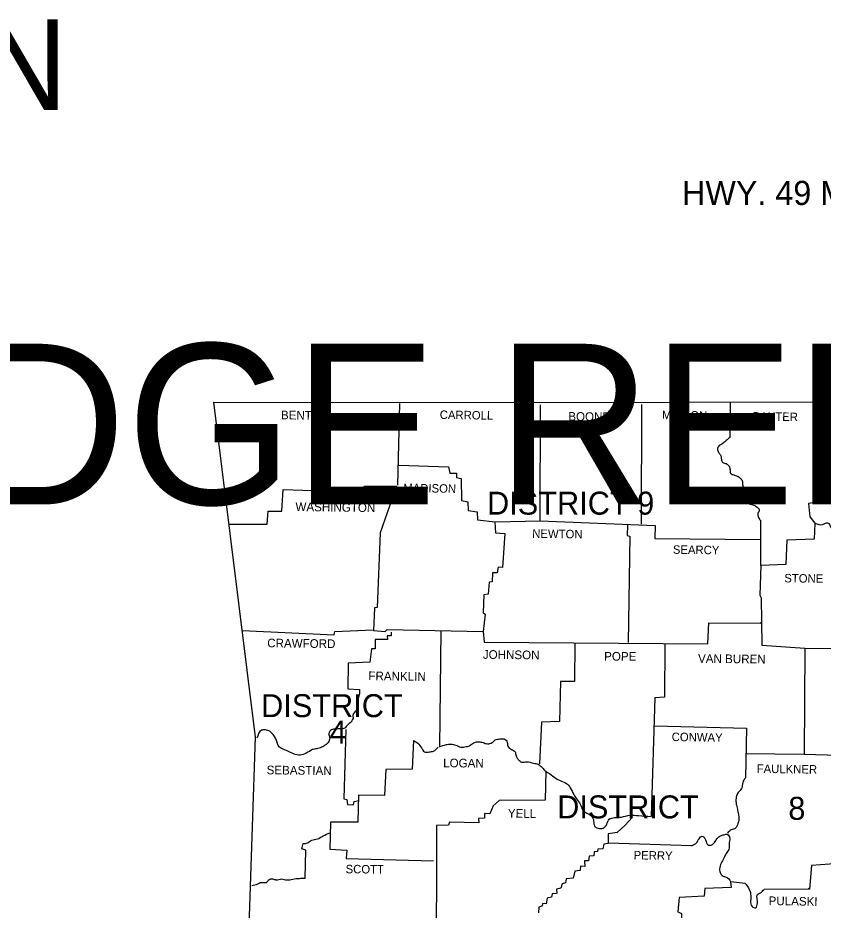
# Model space of a CAD drawing. Extents: x -712 to 3943, y 73 to 2823.
# Drawn here: x 2608.7 to 2999.8, y 1709.8 to 2143 of the extents above; entities that cross this region are included whole.
import ezdxf

# ---------------------------------------------------------------- set-up
doc = ezdxf.new("R2010")
doc.units = 0
for name, color, linetype in [('1', 7, 'Continuous'), ('2', 7, 'Continuous'), ('3', 7, 'Continuous'), ('R_Border', 7, 'Continuous')]:
    doc.layers.add(name, color=color, linetype=linetype)

msp = doc.modelspace()

# ---------------------------------------------------------------- linework, layer by layer
at = {"layer": '1'}
for points in [[(2703.71, 1956.42), (2861.92, 1956.32), (3000.75, 1956.61), (3164.54, 1959.16), (3240.46, 1960.92)], [(2703.71, 1956.42), (2723.96, 1793.81), (2715.15, 1528.37)], [(2794.01, 1955.83), (2793.13, 1916.21)], [(2793.82, 1925.89), (2817.89, 1925.11), (2818.47, 1921.98), (2821.8, 1921.88), (2821.7, 1919.92), (2824.05, 1919.34), (2824.25, 1908.67), (2827.28, 1907.99), (2827.48, 1903.78), (2831.78, 1903.19), (2831.98, 1899.28), (2840.49, 1898.4), (2862.4, 1898.89), (2862.6, 1955.15)], [(2911.62, 1955.34), (2911.33, 1897.22)], [(2954.67, 1956.03), (2954.47, 1939.3)], [(3000.75, 1956.03), (3000.95, 1932.74), (2999.28, 1932.64), (2999.58, 1908.28), (2992.73, 1907.3), (2993.32, 1900.75), (2995.66, 1897.71), (2995.47, 1889.98), (2982.16, 1889.5), (2981.67, 1877.56), (2969.54, 1877.17), (2968.95, 1862.69), (2969.64, 1861.51), (2969.93, 1838.42), (2990.87, 1837.05), (2990.58, 1785.49), (3007.21, 1785), (3007.21, 1732.56), (2994.1, 1731.58), (2993.12, 1720.04), (2971.11, 1719.94)], [(2711.44, 1897.22), (2729.73, 1897.13), (2730.22, 1903.58), (2736.97, 1903.58), (2737.56, 1914.05), (2775.72, 1912.68), (2776.89, 1915.62), (2792.64, 1915.72), (2784.72, 1893.02), (2783.15, 1856.72), (2781.98, 1856.62), (2781.39, 1845.66), (2787.17, 1845.17), (2788.05, 1846.05), (2834.72, 1845.17), (2835.21, 1839.99)], [(2840.29, 1898.2), (2840.68, 1892.92), (2845.18, 1892.63), (2844.01, 1876.19), (2841.96, 1876.29), (2841.56, 1873.65), (2839.22, 1873.65), (2839.12, 1869.14), (2837.65, 1869.05), (2837.16, 1863.27), (2835.01, 1862.98), (2834.72, 1854.17), (2835.69, 1853.49), (2834.72, 1845.17)], [(2862.4, 1898.89), (2918.17, 1896.54), (2918.08, 1890.18), (2969.25, 1889.79)], [(2969.54, 1877.17), (2969.44, 1899.18)], [(2904.77, 1896.83), (2904.67, 1891.75), (2905.94, 1891.45), (2905.16, 1839.79)], [(2969.25, 1849.19), (2969.54, 1849.48)], [(2717.89, 1845.56), (2762.41, 1843.51), (2762.61, 1845.08), (2781.2, 1845.96)], [(2814.17, 1845.56), (2813.48, 1789.11)], [(2835.21, 1839.99), (2943.81, 1839.11), (2944.3, 1849.38), (2969.54, 1849.09)], [(2790, 1844.78), (2790, 1843.02), (2788.14, 1843.02), (2788.24, 1841.26), (2782.27, 1841.16), (2782.18, 1836.76), (2780.51, 1836.76), (2779.63, 1830.2), (2769.06, 1829.71), (2768.97, 1817.29), (2774.64, 1816.9)], [(2879.14, 1839.21), (2879.04, 1820.91), (2872.29, 1820.81), (2871.7, 1801.34), (2863.09, 1801.05), (2862.11, 1780.89)], [(2922.97, 1838.72), (2922.77, 1813.28), (2918.08, 1812.89), (2916.22, 1755.36)], [(2990.87, 1837.05), (3041.16, 1836.76), (3045.46, 1838.81), (3045.17, 1800.56), (3042.24, 1799.29), (3039.59, 1797.04), (3038.71, 1796.16), (3038.62, 1785.2), (3006.62, 1785.2)], [(2767.99, 1797.53), (2767.01, 1763.87), (2768.48, 1763.48), (2768.77, 1761.13), (2771.71, 1760.93), (2772, 1762.6), (2774.35, 1762.99)], [(2917.88, 1799.29), (2962.59, 1798.21), (2962.01, 1774.04)], [(2800.86, 1792.24), (2800.18, 1778.25), (2787.46, 1778.15), (2786.77, 1765.43), (2774.15, 1765.73), (2773.76, 1752.62), (2760.55, 1752.52), (2760.16, 1739.41), (2768.48, 1738.92), (2768.18, 1734.91), (2810.65, 1733.73)], [(2962.1, 1785.88), (2990.58, 1785.49)], [(2865.14, 1777.27), (2864.75, 1763.18), (2842.45, 1763.09), (2839.51, 1760.54), (2837.85, 1756.63), (2835.4, 1756.82), (2835.3, 1754.57), (2832.47, 1754.28), (2832.56, 1752.22), (2818.38, 1752.62), (2817.89, 1751.05), (2812.02, 1750.86), (2811.96, 1733.39)], [(2907.12, 1754.96), (2903.6, 1751.15), (2899.78, 1747.53), (2895.38, 1746.84), (2895.38, 1742.25), (2893.22, 1741.95), (2892.83, 1739.6), (2890.39, 1739.41), (2890.19, 1738.33), (2888.53, 1738.23), (2888.43, 1736.18), (2886.08, 1736.08), (2885.89, 1733.73), (2883.93, 1733.73), (2884.03, 1730.99), (2881.88, 1731.19), (2881.78, 1729.04), (2879.14, 1728.84), (2878.35, 1725.32), (2875.03, 1725.03), (2874.73, 1723.07), (2872.97, 1722.58), (2872.48, 1720.52), (2870.23, 1720.04), (2870.43, 1717.98), (2868.18, 1717.78), (2867.79, 1716.22), (2865.73, 1715.63), (2865.24, 1712.99), (2863.68, 1713.09), (2863.19, 1711.72), (2861.72, 1711.23), (2861.62, 1708.59)], [(2748.32, 1725.22), (2748.62, 1739.02), (2746.66, 1739.6), (2747.25, 1742.25)], [(2935.79, 1741.07), (2895.47, 1742.34)], [(2811.96, 1733.39), (2811.82, 1693.62), (2806.93, 1693.52), (2807.32, 1690.59), (2802.62, 1690.68), (2802.53, 1688.53), (2797.93, 1688.53), (2798.03, 1686.97), (2791.18, 1686.77), (2791.08, 1680.8), (2784.43, 1681.39), (2783.35, 1633.25), (2745.68, 1633.35), (2744.8, 1622.19), (2746.17, 1621.22), (2746.07, 1608.69), (2719.36, 1609.87)], [(2961.91, 1722.77), (2954.86, 1723.56), (2955.16, 1720.92), (2942.34, 1720.43), (2941.95, 1716.61), (2929.91, 1715.93), (2929.23, 1709.08), (2930.99, 1708.2), (2930.99, 1703.7)], [(2992.63, 1720.13), (2993.12, 1720.62)]]:
    msp.add_lwpolyline(points, dxfattribs=at)
for points in [[(2954.47, 1939.3), (2952.71, 1937.83), (2951.15, 1936.46), (2948.8, 1934.8), (2948.5, 1933.23), (2949.29, 1931.66), (2950.07, 1930.39), (2950.36, 1928.63), (2951.05, 1927.16), (2952.71, 1926.58), (2954.08, 1925.31), (2954.57, 1923.54), (2954.77, 1921.88), (2956.33, 1921.1), (2958.09, 1920.51), (2959.76, 1919.34), (2960.54, 1917.87), (2960.73, 1916.01), (2961.42, 1914.54), (2962.2, 1912.78), (2962.4, 1911.31), (2962.2, 1909.85), (2962.59, 1908.48), (2963.87, 1907.11), (2966.12, 1906.42), (2967.68, 1905.44), (2968.76, 1904.07), (2968.07, 1902.41), (2968.17, 1900.94), (2969.05, 1899.18)], [(2995.66, 1897.71), (2999.58, 1897.03), (3001.93, 1897.91), (3003.59, 1895.37), (3004.47, 1893.41), (3005.94, 1890.57), (3008.29, 1889.69), (3010.05, 1888.13), (3010.05, 1886.46), (3008.48, 1884.9), (3007.31, 1883.33), (3007.7, 1881.47), (3008.09, 1878.93), (3008.09, 1876.48), (3007.5, 1874.23), (3007.01, 1872.18), (3007.5, 1870.42), (3009.36, 1870.71), (3011.32, 1872.18), (3013.37, 1872.18), (3015.33, 1871.1), (3017.38, 1869.24), (3019.44, 1869.63), (3021.1, 1870.12), (3023.45, 1870.81), (3025.11, 1869.93), (3026.58, 1868.75), (3028.34, 1866.89), (3030.01, 1865.72), (3032.16, 1864.64), (3034.8, 1863.96), (3037.25, 1862.3), (3037.64, 1859.46), (3037.54, 1857.01), (3037.34, 1853.98), (3037.15, 1850.65), (3037.44, 1847.42), (3038.52, 1845.27), (3039.89, 1842.73), (3040.28, 1840.38), (3040.18, 1836.66)], [(2774.64, 1816.9), (2774.64, 1814.84), (2773.86, 1812.69), (2773.37, 1810.83), (2773.66, 1808.39), (2772.78, 1806.43), (2771.51, 1804.86), (2771.51, 1802.91), (2770.04, 1800.85), (2768.48, 1799.29), (2767.11, 1798.01), (2764.66, 1797.82), (2762.61, 1797.72), (2760.55, 1797.04), (2759.77, 1795.57), (2760.16, 1793.32), (2759.38, 1791.17), (2757.32, 1789.5), (2755.07, 1788.43), (2752.73, 1788.03), (2749.5, 1786.47), (2746.56, 1785.2), (2743.43, 1785.39), (2740.5, 1786.66), (2737.85, 1787.84), (2735.8, 1789.01), (2734.14, 1792.63), (2733.06, 1794.59), (2731.2, 1796.55), (2728.95, 1797.33), (2727.09, 1797.13), (2724.84, 1793.32)], [(2800.86, 1792.24), (2803.02, 1790.87), (2804.68, 1788.62), (2806.15, 1786.76), (2808.59, 1786.66), (2810.55, 1787.06), (2812.8, 1789.01)], [(2813.48, 1789.11), (2816.71, 1790.19), (2819.06, 1790.38), (2821.41, 1789.99), (2823.86, 1789.01), (2826.5, 1789.21), (2828.45, 1789.89), (2830.41, 1791.17), (2832.56, 1791.56), (2834.62, 1791.17), (2836.77, 1790.58), (2839.12, 1791.26), (2840.49, 1792.54), (2842.84, 1792.93), (2844.89, 1792.93), (2846.36, 1791.26), (2846.65, 1789.5), (2848.51, 1787.84), (2850.17, 1786.76), (2850.66, 1784.71), (2851.54, 1783.24), (2852.43, 1782.26), (2853.7, 1781.67), (2855.85, 1781.87), (2859.18, 1781.19), (2861.33, 1780.7), (2863.29, 1779.03), (2865.14, 1777.27)], [(2865.14, 1777.27), (2868.57, 1774.92), (2871.8, 1772.87), (2875.12, 1771.4), (2876.98, 1769.25), (2878.65, 1765.92), (2880.02, 1763.87), (2881.78, 1761.32), (2883.05, 1758.49), (2885.1, 1756.92), (2887.26, 1755.55), (2888.33, 1753.11), (2888.82, 1750.66), (2891.17, 1749.49), (2893.42, 1749.97), (2894.69, 1751.44), (2895.87, 1753.99), (2898.51, 1754.77), (2901.93, 1755.06), (2905.85, 1755.94), (2910.15, 1755.75), (2916.22, 1755.36)], [(2962.01, 1774.04), (2960.73, 1771.79), (2960.15, 1768.86), (2958.58, 1767), (2957.6, 1764.85), (2957.51, 1762.01), (2958, 1759.47), (2958.48, 1757.02), (2958.88, 1754.77), (2958.39, 1751.93), (2957.11, 1749.49), (2955.16, 1748.8), (2953.3, 1747.14)], [(2747.25, 1742.25), (2749.4, 1742.44), (2751.45, 1743.81), (2754.19, 1744.4), (2756.93, 1745.87), (2760.36, 1747.43)], [(2935.79, 1741.07), (2938.23, 1742.44), (2939.5, 1744.5), (2941.07, 1745.77), (2942.63, 1744.01), (2944, 1741.46), (2945.47, 1741.46), (2947.33, 1743.22), (2948.5, 1744.79), (2949.97, 1745.96), (2951.54, 1746.45), (2953.2, 1746.65), (2954.47, 1744.79), (2954.08, 1741.85), (2954.08, 1739.9), (2953.01, 1737.84), (2951.83, 1735.69), (2950.56, 1733.24), (2949.58, 1730.6), (2949.78, 1728.06), (2951.15, 1726.39), (2952.71, 1725.91), (2954.86, 1723.75)], [(2748.32, 1725.22), (2745.49, 1725.12), (2742.26, 1724.73), (2739.32, 1724.34), (2736.68, 1724.83), (2734.23, 1724.44), (2732.57, 1724.83), (2730.52, 1724.34), (2729.34, 1723.17), (2726.9, 1723.17), (2725.13, 1722.38), (2722.3, 1721.7)], [(2961.91, 1722.77), (2963.57, 1720.62), (2964.55, 1717.69), (2964.55, 1714.36), (2965.33, 1711.62), (2966.9, 1711.03), (2967.88, 1713.38), (2967.68, 1715.73), (2967.68, 1717.1), (2969.34, 1718.27), (2971.11, 1719.94)]]:
    msp.add_spline(points, degree=3, dxfattribs=at)

# ---------------------------------------------------------------- texts
at = {"layer": '2'}
for s, height, p in [('ARKANSAS DEPARTMENT OF TRANSPORTATION', 44.0283, (1232.79, 2098.29)), ('HWY. 49 MISSISSIPPI RIVER BRIDGE REHAB. (S)', 78, (969, 1906.78))]:
    msp.add_text(s, height=height, dxfattribs=at).set_placement(p)
for s, height, rotation, p in [('BENTON', 4.207, 359.2527, (2736.48, 1948.1)), ('CARROLL', 4.109, 359.1481, (2813.58, 1948.3)), ('BOONE', 4.207, 359.4001, (2876, 1947.42)), ('MARION', 4.109, 359.1854, (2921.5, 1948.2)), ('BAXTER', 4.109, 359.2559, (2965.53, 1947.51)), ('MADISON', 4.109, 359.0906, (2795.87, 1912.78)), ('WASHINGTON', 4.206, 359.232, (2743.53, 1903.58)), ('NEWTON', 4.109, 359.2717, (2858.49, 1890.57)), ('SEARCY', 4.108, 359.2527, (2926.78, 1882.84)), ('STONE', 4.108, 359.4001, (2980.89, 1868.95)), ('CRAWFORD', 4.206, 359.2771, (2729.83, 1837.44)), ('JOHNSON', 4.207, 359.3514, (2834.52, 1831.87)), ('POPE', 4.207, 359.6155, (2893.42, 1830.99)), ('VAN BUREN', 4.207, 359.3508, (2939.01, 1829.91)), ('FRANKLIN', 4.207, 359.1815, (2778.95, 1821.5)), ('CONWAY', 4.108, 359.0371, (2926.2, 1791.95)), ('LOGAN', 4.207, 359.3969, (2815.25, 1779.23)), ('FAULKNER', 4.109, 359.2486, (2967.49, 1776.49)), ('SEBASTIAN', 4.206, 359.2816, (2729.54, 1775.8)), ('YELL', 4.207, 359.1987, (2846.65, 1754.77)), ('PERRY', 4.109, 359.0858, (2907.71, 1734.52)), ('SCOTT', 4.109, 359.4063, (2767.89, 1727.76)), ('PULASKI', 4.207, 359.053, (2973.26, 1712.31))]:
    msp.add_text(s, height=height, rotation=rotation, dxfattribs=at).set_placement(p)
at = {"layer": '3'}
for s, height, p in [('DISTRICT 9', 11.154, (2836.57, 1901.82)), ('DISTRICT', 11.154, (2726.87, 1803.53)), ('4', 11.15, (2760.08, 1790.72)), ('DISTRICT', 11.154, (2870.62, 1754.38)), ('8', 11.15, (2982.85, 1753.69))]:
    msp.add_text(s, height=height, dxfattribs=at).set_placement(p)
at = {"layer": 'R_Border'}
msp.add_text('HWY. 49 MISSISSIPPI  RIVER BRIDGE REHAB. (S)', height=11.724, dxfattribs=at).set_placement((2931.28, 2052.13))

doc.saveas('drawing.dxf')
